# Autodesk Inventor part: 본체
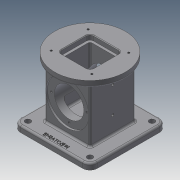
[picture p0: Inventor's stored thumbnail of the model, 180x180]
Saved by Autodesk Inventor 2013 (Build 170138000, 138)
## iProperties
Created: 2021-05
Part Number: 본체
Material: Generic
Document SubType Name: Modeling
Designer: user
Density: 1 g/cm^3
Mass: 463.439 g
Surface Area: 896.361 cm^2
Volume: 463.439 cm^3
Author: user
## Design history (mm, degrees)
sketch "스케치1"
  geometry: L1 (62.5, -62.5)-(-62.5, -62.5); L2 (-62.5, -62.5)-(-62.5, 62.5); L3 (-62.5, 62.5)-(62.5, 62.5); L4 (62.5, 62.5)-(62.5, -62.5); L5 (62.5, -62.5)-(-62.5, 62.5); L6 (-62.5, -62.5)-(62.5, 62.5); 1 further point
  constraints: 12 end point, 2 midpoint, 2 parallel, 1 horizontal, 1 perpendicular
  dimensions: "d0" = 125 distance of L1.start L1.end; "d2" = 125 distance of L1.end L2.end
extrude "돌출1" new body sketch "스케치1" distance "d3" = 10; taper "d4" = 0 deg
node "작업 평면2"
sketch "스케치2"
  geometry: C1 r 57.5 at (0, 0); 1 further point
  constraints: 1 centre point, 1 coincident
  dimensions: "d7" = 115 diameter of C1
extrude "돌출2" join sketch "스케치2" distance "d8" = 10; taper "d9" = 0 deg
sketch "스케치3"
  geometry: L1 (-37, 37)-(37, 37); L2 (37, 37)-(37, -37); L3 (37, -37)-(-37, -37); L4 (-37, -37)-(-37, 37); L5 (-37, 37)-(37, -37); L6 (37, 37)-(-37, -37); 1 further point
  constraints: 12 end point, 2 midpoint, 2 parallel, 1 horizontal, 1 perpendicular
  dimensions: "d10" = 74 distance of L1.start L1.end; "d12" = 74 distance of L1.end L2.end
extrude "돌출3" join sketch "스케치3" stored distance "d13" = 10; taper "d14" = 0 deg
sketch "스케치4"
  geometry: L1 (-26, 26)-(26, 26); L2 (26, 26)-(26, -26); L3 (26, -26)-(-26, -26); L4 (-26, -26)-(-26, 26); L5 (-26, 26)-(26, -26); L6 (26, 26)-(-26, -26); C1 r 57.5 at (0, 0) reference
  constraints: 12 end point, 2 midpoint, 2 parallel, 1 horizontal, 1 perpendicular
  dimensions: "d15" = 52 distance of L2.end L3.end; "d16" = 52 distance of L1.end L2.end
extrude "돌출4" cut sketch "스케치4" distance "d17" = 8; taper "d18" = 0 deg
sketch "스케치5"
  geometry: L1 (-22, 22)-(22, 22); L2 (22, 22)-(22, -22); L3 (22, -22)-(-22, -22); L4 (-22, -22)-(-22, 22); L5 (-22, 22)-(22, -22); L6 (22, 22)-(-22, -22); 1 further point
  constraints: 12 end point, 2 midpoint, 2 parallel, 1 horizontal, 1 perpendicular
  dimensions: "d19" = 44 distance of L1.start L1.end; "d21" = 44 distance of L1.end L2.end
extrude "돌출5" cut sketch "스케치5" distance "d22" = 74; taper "d23" = 0 deg
sketch "스케치6"
  geometry: C1 r 28 at (0, 0); 1 further point
  constraints: 1 centre point, 1 coincident
  dimensions: "d24" = 56 diameter of C1
extrude "돌출6" cut sketch "스케치6" distance "d25" = 18; taper "d26" = 0 deg
sketch "스케치7"
  geometry: L1 (0, 0)-(0, 88) reference; C1 r 35 at (37, 44); 2 further points
  constraints: 1 centre point, 1 horizontal alignment, 1 midpoint
  dimensions: "d27" = 70 diameter of C1
extrude "돌출7" cut sketch "스케치7" distance "d28" = 3; taper "d29" = 0 deg
sketch "스케치8"
  geometry: C1 r 35 at (0, 0) reference; C2 r 24 at (0, 0); 1 further point
  constraints: 1 centre point, 1 coincident
  dimensions: "d30" = 48 diameter of C2
extrude "돌출8" cut sketch "스케치8" distance "d31" = 100; taper "d32" = 0 deg
fillet "모깎기1" dims "d33" = 12
sketch "스케치9"
  geometry: A1 r 12 centre (-50.5, 50.5) between (-50.5, 62.5) and (-62.5, 50.5) reference; A2 r 12 centre (-50.5, -50.5) between (-62.5, -50.5) and (-50.5, -62.5) reference; A3 r 12 centre (50.5, -50.5) between (50.5, -62.5) and (62.5, -50.5) reference; A4 r 12 centre (50.5, 50.5) between (62.5, 50.5) and (50.5, 62.5) reference; 5 further points
  constraints: 4 coincident
hole "구멍1" sketch "스케치9" at (-50.5, 50.5), (-50.5, -50.5), (50.5, -50.5), (50.5, 50.5) diameter "d34" = 9; stored, may be unused: countersink angle "d38" = 90 deg, drill point angle "d40" = 118 deg; dims "d35" = 6, "d36" = 4, "d37" = 2, "d39" = 8
sketch "스케치10"
  geometry: C1 r 24 at (0, 0) reference; C2 r 35 at (0, 0) reference; A1 r 29 centre (0, 0) between (0, 29) and (-29, 0); 3 further points
  constraints: 4 point on circle, 2 horizontal alignment, 2 vertical alignment, 1 centre point, 1 coincident
  dimensions: "d41" = 58 diameter of A1
hole "구멍2" sketch "스케치10" at (0, 29), (-29, 0), (0, -29), (29, 0) diameter "d42" = 3.242; stored, may be unused: countersink angle "d46" = 90 deg, drill point angle "d48" = 118 deg; dims "d43" = 8, "d44" = 4, "d45" = 2, "d47" = 10
sketch "스케치11"
  geometry: L1 (-33, 30)-(33, 30); L2 (33, 30)-(33, -30); L3 (33, -30)-(-33, -30); L4 (-33, -30)-(-33, 30); L5 (-33, 30)-(33, -30); L6 (33, 30)-(-33, -30); C1 r 57.5 at (0, 0) reference; 4 further points
  constraints: 12 end point, 4 coincident, 2 midpoint, 2 parallel, 1 horizontal, 1 perpendicular
  dimensions: "d49" = 66 distance of L1.start L1.end; "d51" = 60 distance of L1.end L2.end
hole "구멍3" sketch "스케치11" at (-33, 30), (-33, -30), (33, -30), (33, 30) diameter "d52" = 3.242; stored, may be unused: countersink angle "d56" = 90 deg, drill point angle "d58" = 118 deg; dims "d53" = 8, "d54" = 4, "d55" = 2, "d57" = 10
node "작업 평면3"
sketch "스케치12"
  geometry: 2 further points
  constraints: 1 vertical alignment, 1 other
  dimensions: "d60" = 55 distance of point (0, 55) point (0, 0)
feature "엠보싱1" sketch "스케치12" dims "d0" = 125, "d2" = 125, "d13" = 10, "d14" = 0, "d61" = 0.5, "d62" = 0
sketch "스케치13"
  geometry: 3 further points
  constraints: 2 vertical alignment
  dimensions: "d63" = 37 distance of point (37, -10) point (37, 27); "d64" = 43 distance of point (37, 27) point (37, 70)
hole "구멍4" sketch "스케치13" at (37, 27), (37, 70) diameter "d65" = 4.134; stored, may be unused: countersink angle "d69" = 90 deg, drill point angle "d71" = 118 deg; dims "d66" = 30, "d67" = 4, "d68" = 2, "d70" = 30
fillet "모깎기2" dims "d72" = 3
fillet "모깎기3" dims "d73" = 3
fillet "모깎기4" dims "d74" = 3
fillet "모깎기5" dims "d75" = 6
fillet "모깎기6" dims "d76" = 3
chamfer "모따기1" distance "d77" = 1; stored, may be unused: second distance "d78" = 2, angle "d79" = 45 deg
feature "면 기울기1" dims angle "d80" = 10 deg
fillet "모깎기7" dims "d81" = 3
fillet "모깎기8" dims "d82" = 3
fillet "모깎기9" dims "d83" = 3
fillet "모깎기10" dims "d84" = 3
node "솔리드1"
mirror "대칭1"
mirror "대칭2"
other parameters: "d6" = 108, "d59" = 24.75
